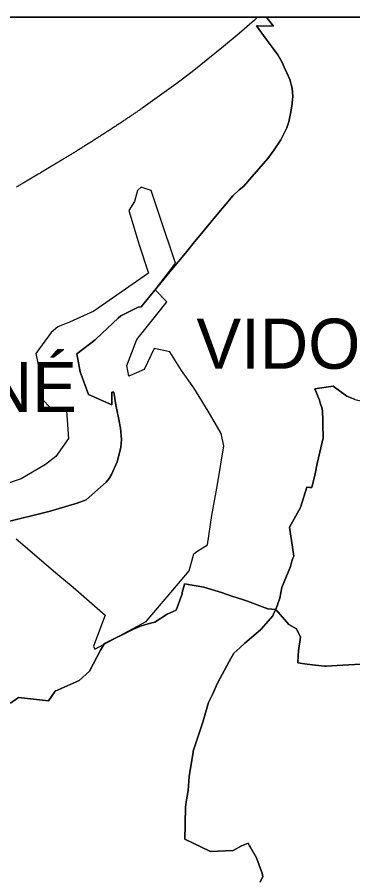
# Model space of a CAD drawing. Extents: x -759276 to -751881, y -1176141 to -1171097.
# Drawn here: x -755760 to -754995, y -1173060 to -1171097 of the extents above; entities that cross this region are included whole.
import ezdxf

# ---------------------------------------------------------------- set-up
doc = ezdxf.new("R2010")
doc.units = 0
for name, color, linetype in [('A_HRU', 7, 'Continuous'), ('A_OBCE', 7, 'Continuous'), ('A_SILNICE', 7, 'Continuous'), ('A_USES', 7, 'Continuous'), ('AA_vyrezy', 7, 'Continuous')]:
    doc.layers.add(name, color=color, linetype=linetype)

msp = doc.modelspace()

# ---------------------------------------------------------------- linework, layer by layer
at = {"layer": 'A_HRU'}
for points in [[(-759275.6, -1176140.6), (-759275.6, -1171097.2), (-751880.9, -1171097.2), (-751880.9, -1176140.6)], [(-751880.9, -1172828.3), (-753894.3, -1172828.3), (-753894.3, -1171097.2), (-759275.6, -1171097.2), (-759275.6, -1176140.6), (-753894.3, -1176140.6), (-753894.3, -1174884.8), (-751880.9, -1174884.8)]]:
    msp.add_lwpolyline(points, close=True, dxfattribs=at)
at = {"layer": 'A_OBCE'}
for p, q in [((-755191.2, -1171097.2), (-756678.2, -1171097.2)), ((-755191.2, -1171097.2), (-755189.6, -1171099.3)), ((-754699.6, -1171097.2), (-755191.2, -1171097.2)), ((-755189.6, -1171099.3), (-755181.2, -1171110.1)), ((-755214.5, -1171117.1), (-755192, -1171147)), ((-755181.2, -1171110.1), (-755175.1, -1171118)), ((-755192, -1171147), (-755187.5, -1171153.1)), ((-755165.3, -1171183.2), (-755156.2, -1171199.1)), ((-755156.2, -1171199.1), (-755151, -1171211.1)), ((-755138.5, -1171239.2), (-755132.9, -1171259.5)), ((-755131.7, -1171278), (-755132.9, -1171259.5)), ((-755132.9, -1171259.5), (-755131.7, -1171278)), ((-755133.5, -1171300.6), (-755131.7, -1171278)), ((-755131.7, -1171278), (-755133.5, -1171300.6)), ((-755144.9, -1171349.4), (-755140.5, -1171336.4)), ((-755140.5, -1171336.4), (-755144.9, -1171349.4)), ((-755144.9, -1171349.4), (-755153.8, -1171368.4)), ((-755153.8, -1171368.4), (-755158.5, -1171377.5)), ((-755158.5, -1171377.5), (-755174, -1171400.1)), ((-755174, -1171400.1), (-755188.2, -1171419.5)), ((-755188.2, -1171419.5), (-755208.8, -1171443.2)), ((-755208.8, -1171443.2), (-755229.7, -1171466.9)), ((-755229.7, -1171466.9), (-755243.2, -1171482.6)), ((-755253.7, -1171491.7), (-755268.3, -1171505.3)), ((-755243.2, -1171482.6), (-755253.7, -1171491.7)), ((-755268.3, -1171505.3), (-755276.4, -1171515.1)), ((-755296.6, -1171538.4), (-755279.2, -1171518.2)), ((-755279.2, -1171518.2), (-755296.6, -1171538.4)), ((-755276.4, -1171515.1), (-755279.2, -1171518.2)), ((-755408.1, -1171673.9), (-755375.8, -1171635.8)), ((-755411.9, -1171678.4), (-755408.1, -1171673.9)), ((-755529.5, -1171784.5), (-755579.6, -1171831.8)), ((-755624.1, -1171865.9), (-755582.1, -1171833.7)), ((-755624.1, -1171865.9), (-755616.1, -1171906.8)), ((-755039.3, -1171939.7), (-755081.3, -1171945.8)), ((-755008.6, -1171962.4), (-755039.3, -1171939.7)), ((-755544.1, -1171982), (-755544.3, -1171953.2)), ((-755070.9, -1171971.5), (-755081.3, -1171945.8)), ((-755081.3, -1171945.8), (-755070.9, -1171971.5)), ((-755067.9, -1171980.7), (-755070.9, -1171971.5)), ((-755065.4, -1171988.3), (-755067.9, -1171980.7)), ((-755527.8, -1172015.9), (-755533.2, -1171989.5)), ((-755533.2, -1171989.5), (-755527.8, -1172015.9)), ((-755062.8, -1172018.3), (-755063.3, -1172028)), ((-755523.6, -1172079.7), (-755532.1, -1172112.1)), ((-755069.9, -1172090.5), (-755075.9, -1172116.5)), ((-755532.1, -1172112.1), (-755544.6, -1172140.9)), ((-755075.9, -1172116.5), (-755080.1, -1172140.1)), ((-755080.1, -1172140.1), (-755088.2, -1172170.7)), ((-755556.8, -1172158.7), (-755602.9, -1172199.5)), ((-755556.8, -1172158.7), (-755550, -1172150.3)), ((-755099.4, -1172170.3), (-755113.8, -1172216.8)), ((-755098.4, -1172170.4), (-755092.7, -1172170.6)), ((-755088.2, -1172170.7), (-755092.7, -1172170.6)), ((-755602.9, -1172199.5), (-755622.9, -1172206.8)), ((-755685.1, -1172225.2), (-755622.9, -1172206.8)), ((-755622.9, -1172206.8), (-755685.1, -1172225.2)), ((-755139.1, -1172261.5), (-755113.8, -1172216.8)), ((-755113.8, -1172216.8), (-755139.1, -1172261.5)), ((-755788.6, -1172250.8), (-755685.1, -1172225.2)), ((-755685.1, -1172225.2), (-755788.6, -1172250.8)), ((-755139.1, -1172261.5), (-755129.2, -1172327.7)), ((-755129.2, -1172327.7), (-755131, -1172332.4)), ((-755379.4, -1172394.5), (-755383.6, -1172410.6)), ((-755383.6, -1172410.6), (-755379.4, -1172394.5)), ((-755379.4, -1172394.5), (-755378.4, -1172390.8)), ((-755245.8, -1172427), (-755270.4, -1172418.9)), ((-755270.4, -1172418.9), (-755245.8, -1172427)), ((-755160.9, -1172423.4), (-755169.9, -1172449.7)), ((-755418.2, -1172460), (-755397.6, -1172451)), ((-755174.6, -1172458.1), (-755169.9, -1172449.7)), ((-755169.9, -1172449.7), (-755140.7, -1172483.7)), ((-755418.2, -1172460), (-755446.1, -1172478.2)), ((-755446.1, -1172478.2), (-755418.2, -1172460)), ((-755177.3, -1172463.6), (-755203.3, -1172494.5)), ((-755495, -1172494.6), (-755560.6, -1172527.4)), ((-755560.6, -1172527.4), (-755495, -1172494.6)), ((-755495, -1172494.6), (-755479.1, -1172487.6)), ((-755479.1, -1172487.6), (-755469, -1172484.6)), ((-755469, -1172484.6), (-755455.8, -1172480.6)), ((-755455.8, -1172480.6), (-755446.1, -1172478.2)), ((-755203.3, -1172494.5), (-755205.1, -1172496)), ((-755241, -1172526.4), (-755205.1, -1172496)), ((-755205.1, -1172496), (-755241, -1172526.4)), ((-755560.6, -1172527.4), (-755570, -1172542.4)), ((-755570, -1172542.4), (-755560.6, -1172527.4)), ((-755241.6, -1172527), (-755241, -1172526.4)), ((-755241, -1172526.4), (-755241.6, -1172527)), ((-755570, -1172542.4), (-755595.4, -1172590.4)), ((-755595.4, -1172590.4), (-755570, -1172542.4)), ((-755276.3, -1172568.6), (-755302.9, -1172617.6)), ((-755119.3, -1172554.4), (-755120.2, -1172571.1)), ((-755120.2, -1172571.1), (-755104.4, -1172573.2)), ((-755618.7, -1172611.4), (-755595.4, -1172590.4)), ((-755104.4, -1172573.2), (-755086.9, -1172575.5)), ((-755055.1, -1172579), (-755017.6, -1172576.6)), ((-754976.1, -1172574.1), (-755017.6, -1172576.6)), ((-755017.6, -1172576.6), (-754976.1, -1172574.1)), ((-755673.7, -1172636), (-755618.7, -1172611.4)), ((-755302.9, -1172617.6), (-755314.9, -1172643.6)), ((-755775.2, -1172663.6), (-755756.9, -1172650.2)), ((-755314.9, -1172643.6), (-755323.3, -1172661.6)), ((-755367.7, -1172830.6), (-755358.9, -1172774.9)), ((-755358.9, -1172774.9), (-755367.7, -1172830.6)), ((-755358.7, -1172773.3), (-755358.9, -1172774.9)), ((-755369.8, -1172862.6), (-755367.7, -1172830.6)), ((-755367.7, -1172830.6), (-755369.8, -1172862.6)), ((-755369.8, -1172862.6), (-755374.3, -1172888.7)), ((-755376.8, -1172937.9), (-755376.4, -1172901.1)), ((-755376.4, -1172901.1), (-755376.8, -1172937.9)), ((-755374.3, -1172888.7), (-755376.4, -1172901.1)), ((-755377.5, -1172973.7), (-755376.9, -1172941.1)), ((-755376.9, -1172941.1), (-755377.5, -1172973.7)), ((-755376.9, -1172941.1), (-755376.8, -1172937.9)), ((-755376.8, -1172937.9), (-755376.9, -1172941.1)), ((-755377.5, -1172973.7), (-755319.1, -1173002.3)), ((-755319.1, -1173002.3), (-755267.7, -1172999.5)), ((-755267.7, -1172999.5), (-755248.1, -1172989.1)), ((-755229.9, -1172989), (-755228.3, -1172991.7)), ((-755228.3, -1172991.7), (-755214.3, -1173016.4)), ((-755206, -1173071.7), (-755199.5, -1173059.1)), ((-755199.5, -1173059.1), (-755206, -1173071.7))]:
    msp.add_line(p, q, dxfattribs=at)
for points in [[(-755187.5, -1171153.1), (-755192, -1171147), (-755214.5, -1171117.1), (-755212.9, -1171117.2), (-755175.1, -1171118), (-755181.2, -1171110.1), (-755189.6, -1171099.3), (-755191.2, -1171097.2)], [(-755175.1, -1171118), (-755212.9, -1171117.2), (-755214.5, -1171117.1)], [(-755151, -1171211.1), (-755156.2, -1171199.1), (-755165.3, -1171183.2), (-755176.1, -1171168.3), (-755187.5, -1171153.1)], [(-755187.5, -1171153.1), (-755176.1, -1171168.3), (-755165.3, -1171183.2)], [(-755132.9, -1171259.5), (-755138.5, -1171239.2), (-755144.7, -1171224.3), (-755151, -1171211.1)], [(-755151, -1171211.1), (-755144.7, -1171224.3), (-755138.5, -1171239.2)], [(-755140.5, -1171336.4), (-755136.4, -1171317.4), (-755133.5, -1171300.6)], [(-755133.5, -1171300.6), (-755136.4, -1171317.4), (-755140.5, -1171336.4)], [(-755253.7, -1171491.7), (-755243.2, -1171482.6), (-755229.7, -1171466.9), (-755208.8, -1171443.2), (-755188.2, -1171419.5), (-755174, -1171400.1), (-755158.5, -1171377.5), (-755153.8, -1171368.4), (-755144.9, -1171349.4)], [(-755279.2, -1171518.2), (-755276.4, -1171515.1), (-755268.3, -1171505.3), (-755253.7, -1171491.7)], [(-755296.6, -1171538.4), (-755358.7, -1171613.7), (-755375.8, -1171635.8), (-755408.1, -1171673.9), (-755411.9, -1171678.4), (-755477.4, -1171758.1), (-755483.7, -1171758.9), (-755523.5, -1171778.9), (-755529.5, -1171784.5)], [(-755375.8, -1171635.8), (-755358.7, -1171613.7), (-755296.6, -1171538.4)], [(-755529.5, -1171784.5), (-755523.5, -1171778.9), (-755483.7, -1171758.9), (-755477.4, -1171758.1), (-755411.9, -1171678.4)], [(-755582.1, -1171833.7), (-755579.6, -1171831.8), (-755529.5, -1171784.5)], [(-755579.6, -1171831.8), (-755582.1, -1171833.7), (-755624.1, -1171865.9)], [(-755597.5, -1171958.4), (-755616.1, -1171906.8), (-755624.1, -1171865.9)], [(-755616.1, -1171906.8), (-755597.5, -1171958.4), (-755544.1, -1171982)], [(-755081.3, -1171945.8), (-755039.3, -1171939.7), (-755008.6, -1171962.4)], [(-755533.2, -1171989.5), (-755534.8, -1171981.9), (-755539.3, -1171953.3), (-755544.3, -1171953.2), (-755544.1, -1171982), (-755597.5, -1171958.4)], [(-755544.3, -1171953.2), (-755539.3, -1171953.3), (-755534.8, -1171981.9), (-755533.2, -1171989.5)], [(-755008.6, -1171962.4), (-754992.9, -1171968.8), (-754990.3, -1171969.9), (-754951.7, -1171978.1)], [(-754990.3, -1171969.9), (-754992.9, -1171968.8), (-755008.6, -1171962.4)], [(-755070.9, -1171971.5), (-755067.9, -1171980.7), (-755065.4, -1171988.3)], [(-755075.9, -1172116.5), (-755069.9, -1172090.5), (-755062.3, -1172057.3), (-755063.3, -1172028), (-755062.8, -1172018.3), (-755064, -1171996.1), (-755065.4, -1171988.3)], [(-755065.4, -1171988.3), (-755064, -1171996.1), (-755062.8, -1172018.3)], [(-755522.4, -1172061.4), (-755524.7, -1172035.5), (-755527.8, -1172015.9)], [(-755527.8, -1172015.9), (-755524.7, -1172035.5), (-755522.4, -1172061.4), (-755523.6, -1172079.7)], [(-755063.3, -1172028), (-755062.3, -1172057.3), (-755069.9, -1172090.5)], [(-755532.1, -1172112.1), (-755523.6, -1172079.7), (-755522.4, -1172061.4)], [(-755550, -1172150.3), (-755544.6, -1172140.9), (-755532.1, -1172112.1)], [(-755092.7, -1172170.6), (-755088.2, -1172170.7), (-755080.1, -1172140.1), (-755075.9, -1172116.5)], [(-755544.6, -1172140.9), (-755550, -1172150.3), (-755556.8, -1172158.7)], [(-755622.9, -1172206.8), (-755602.9, -1172199.5), (-755556.8, -1172158.7)], [(-755113.8, -1172216.8), (-755099.4, -1172170.3), (-755098.4, -1172170.4)], [(-755092.7, -1172170.6), (-755098.4, -1172170.4), (-755099.4, -1172170.3)], [(-755137, -1172351.6), (-755133.5, -1172338.9), (-755131, -1172332.4), (-755129.2, -1172327.7), (-755139.1, -1172261.5)], [(-755131, -1172332.4), (-755133.5, -1172338.9), (-755137, -1172351.6)], [(-755169.9, -1172449.7), (-755160.9, -1172423.4), (-755156.5, -1172399.1), (-755137, -1172351.6)], [(-755137, -1172351.6), (-755156.5, -1172399.1), (-755160.9, -1172423.4)], [(-755270.4, -1172418.9), (-755294.4, -1172411), (-755334, -1172398.2), (-755378.4, -1172390.8), (-755379.4, -1172394.5)], [(-755378.4, -1172390.8), (-755334, -1172398.2), (-755294.4, -1172411), (-755270.4, -1172418.9)], [(-755383.6, -1172410.6), (-755383.7, -1172414), (-755397.6, -1172451), (-755418.2, -1172460)], [(-755397.6, -1172451), (-755383.7, -1172414), (-755383.6, -1172410.6)], [(-755234.7, -1172430.7), (-755236.9, -1172429.9), (-755245.8, -1172427)], [(-755245.8, -1172427), (-755236.9, -1172429.9), (-755234.7, -1172430.7)], [(-755169.9, -1172449.7), (-755188.6, -1172448.2), (-755200.6, -1172443.7), (-755234.7, -1172430.7)], [(-755234.7, -1172430.7), (-755200.6, -1172443.7), (-755188.6, -1172448.2), (-755169.9, -1172449.7)], [(-755169.9, -1172449.7), (-755174.6, -1172458.1), (-755177.3, -1172463.6)], [(-755118.7, -1172543.7), (-755113.6, -1172513), (-755122.9, -1172494), (-755140.7, -1172483.7), (-755169.9, -1172449.7)], [(-755205.1, -1172496), (-755203.3, -1172494.5), (-755177.3, -1172463.6), (-755174.6, -1172458.1)], [(-755469, -1172484.6), (-755479.1, -1172487.6), (-755495, -1172494.6)], [(-755446.1, -1172478.2), (-755455.8, -1172480.6), (-755469, -1172484.6)], [(-755140.7, -1172483.7), (-755122.9, -1172494), (-755113.6, -1172513)], [(-755113.6, -1172513), (-755118.7, -1172543.7), (-755119.3, -1172554.4)], [(-755241.6, -1172527), (-755252.3, -1172536.7), (-755265.6, -1172548.9), (-755276.3, -1172568.6)], [(-755265.6, -1172548.9), (-755252.3, -1172536.7), (-755241.6, -1172527)], [(-755302.9, -1172617.6), (-755276.3, -1172568.6), (-755265.6, -1172548.9)], [(-755120.2, -1172571.1), (-755119.3, -1172554.4), (-755118.7, -1172543.7)], [(-755017.6, -1172576.6), (-755055.1, -1172579), (-755059.2, -1172579), (-755086.9, -1172575.5), (-755104.4, -1172573.2), (-755120.2, -1172571.1)], [(-755595.4, -1172590.4), (-755618.7, -1172611.4), (-755673.7, -1172636), (-755688.4, -1172658)], [(-755086.9, -1172575.5), (-755059.2, -1172579), (-755055.1, -1172579)], [(-755323.3, -1172661.6), (-755314.9, -1172643.6), (-755302.9, -1172617.6)], [(-755688.4, -1172658), (-755756.9, -1172650.2), (-755775.2, -1172663.6)], [(-755756.9, -1172650.2), (-755688.4, -1172658), (-755673.7, -1172636)], [(-755358.9, -1172774.9), (-755358.7, -1172773.3), (-755336.7, -1172707), (-755323.3, -1172661.6)], [(-755323.3, -1172661.6), (-755336.7, -1172707), (-755358.7, -1172773.3)], [(-755376.4, -1172901.1), (-755374.3, -1172888.7), (-755369.8, -1172862.6)], [(-755248.1, -1172989.1), (-755267.7, -1172999.5), (-755319.1, -1173002.3), (-755377.5, -1172973.7)], [(-755229.9, -1172989), (-755233.2, -1172983.1), (-755248.1, -1172989.1)], [(-755248.1, -1172989.1), (-755233.2, -1172983.1), (-755229.9, -1172989)], [(-755214.3, -1173016.4), (-755228.3, -1172991.7), (-755229.9, -1172989)], [(-755199.5, -1173059.1), (-755201.1, -1173051.5), (-755204.8, -1173041.6), (-755214.3, -1173016.4)], [(-755214.3, -1173016.4), (-755204.8, -1173041.6), (-755201.1, -1173051.5), (-755199.5, -1173059.1)]]:
    msp.add_lwpolyline(points, dxfattribs=at)
at = {"layer": 'A_SILNICE'}
msp.add_lwpolyline([(-755211.9, -1171097.2), (-755219.1, -1171103.7), (-755253.8, -1171134.1), (-755289.1, -1171163.9), (-755324.9, -1171193.1), (-755361.2, -1171221.7), (-755398, -1171249.7), (-755435.2, -1171277), (-755473, -1171303.7), (-755474.8, -1171305), (-755476.6, -1171306.2), (-755478.4, -1171307.5), (-755480.2, -1171308.7), (-755482, -1171310), (-755483.8, -1171311.2), (-755485.6, -1171312.5), (-755487.4, -1171313.7), (-755489.3, -1171315), (-755491.1, -1171316.2), (-755492.9, -1171317.4), (-755494.7, -1171318.7), (-755496.5, -1171319.9), (-755498.3, -1171321.2), (-755500.2, -1171322.4), (-755502, -1171323.6), (-755503.8, -1171324.9), (-755505.6, -1171326.1), (-755507.5, -1171327.3), (-755509.3, -1171328.5), (-755511.1, -1171329.8), (-755512.9, -1171331), (-755514.8, -1171332.2), (-755516.6, -1171333.4), (-755518.4, -1171334.7), (-755520.3, -1171335.9), (-755522.1, -1171337.1), (-755523.9, -1171338.3), (-755525.7, -1171339.5), (-755527.6, -1171340.8), (-755529.4, -1171342), (-755531.3, -1171343.2), (-755533.1, -1171344.4), (-755534.9, -1171345.6), (-755536.8, -1171346.8), (-755538.6, -1171348), (-755540.4, -1171349.2), (-755542.3, -1171350.4), (-755544.1, -1171351.6), (-755546, -1171352.8), (-755547.8, -1171354), (-755549.7, -1171355.2), (-755551.5, -1171356.4), (-755553.3, -1171357.6), (-755555.2, -1171358.8), (-755557, -1171360), (-755558.9, -1171361.2), (-755560.7, -1171362.4), (-755562.6, -1171363.6), (-755564.4, -1171364.8), (-755566.3, -1171366), (-755568.1, -1171367.2), (-755570, -1171368.4), (-755571.8, -1171369.6), (-755573.7, -1171370.7), (-755575.5, -1171371.9), (-755577.4, -1171373.1), (-755579.3, -1171374.3), (-755581.1, -1171375.5), (-755583, -1171376.7), (-755584.8, -1171377.8), (-755586.7, -1171379), (-755588.5, -1171380.2), (-755590.4, -1171381.4), (-755592.3, -1171382.5), (-755594.1, -1171383.7), (-755596, -1171384.9), (-755597.8, -1171386.1), (-755599.7, -1171387.2), (-755601.6, -1171388.4), (-755603.4, -1171389.6), (-755605.3, -1171390.7), (-755607.2, -1171391.9), (-755609, -1171393.1), (-755610.9, -1171394.2), (-755612.8, -1171395.4), (-755614.6, -1171396.6), (-755616.5, -1171397.7), (-755618.4, -1171398.9), (-755620.2, -1171400), (-755622.1, -1171401.2), (-755624, -1171402.4), (-755625.8, -1171403.5), (-755627.7, -1171404.7), (-755629.6, -1171405.8), (-755631.5, -1171407), (-755633.3, -1171408.1), (-755635.2, -1171409.3), (-755637.1, -1171410.5), (-755639, -1171411.6), (-755640.8, -1171412.8), (-755642.7, -1171413.9), (-755644.6, -1171415.1), (-755646.5, -1171416.2), (-755648.3, -1171417.3), (-755650.2, -1171418.5), (-755652.1, -1171419.6), (-755654, -1171420.8), (-755655.8, -1171421.9), (-755657.7, -1171423.1), (-755659.6, -1171424.2), (-755661.5, -1171425.4), (-755663.4, -1171426.5), (-755665.2, -1171427.6), (-755667.1, -1171428.8), (-755669, -1171429.9), (-755670.9, -1171431.1), (-755672.8, -1171432.2), (-755674.7, -1171433.3), (-755676.5, -1171434.5), (-755678.4, -1171435.6), (-755680.3, -1171436.7), (-755682.2, -1171437.9), (-755684.1, -1171439), (-755686, -1171440.1), (-755687.9, -1171441.3), (-755689.7, -1171442.4), (-755691.6, -1171443.5), (-755693.5, -1171444.7), (-755695.4, -1171445.8), (-755697.3, -1171446.9), (-755699.2, -1171448), (-755701.1, -1171449.2), (-755703, -1171450.3), (-755704.9, -1171451.4), (-755706.7, -1171452.6), (-755708.6, -1171453.7), (-755710.5, -1171454.8), (-755712.4, -1171455.9), (-755714.3, -1171457.1), (-755716.2, -1171458.2), (-755718.1, -1171459.3), (-755720, -1171460.4), (-755721.9, -1171461.5), (-755723.8, -1171462.7), (-755725.7, -1171463.8), (-755727.6, -1171464.9), (-755729.4, -1171466), (-755731.3, -1171467.1), (-755733.2, -1171468.3), (-755735.1, -1171469.4), (-755737, -1171470.5), (-755738.9, -1171471.6), (-755740.8, -1171472.7), (-755742.7, -1171473.9), (-755744.6, -1171475), (-755746.5, -1171476.1), (-755748.4, -1171477.2), (-755750.3, -1171478.3), (-755752.2, -1171479.4), (-755754.1, -1171480.5), (-755756, -1171481.7), (-755757.9, -1171482.8), (-755759.8, -1171483.9), (-755761.7, -1171485)], dxfattribs=at)
at = {"layer": 'A_USES'}
msp.add_lwpolyline([(-755762.3, -1172288), (-755667, -1172369.5), (-755632, -1172398.5), (-755559.6, -1172462.5), (-755585.6, -1172532.9), (-755583.2, -1172540.2), (-755465.9, -1172477), (-755392.4, -1172390.2), (-755368.1, -1172361.2), (-755357.1, -1172322.4), (-755350.3, -1172317.4), (-755326.2, -1172302.2), (-755316, -1172235.1), (-755303.5, -1172164.1), (-755288.7, -1172075.9), (-755295, -1172047.8), (-755324.6, -1171997), (-755357.4, -1171943.2), (-755385.5, -1171904.1), (-755412, -1171861.2), (-755447.2, -1171853.4), (-755470.6, -1171901.8), (-755505.7, -1171916.6), (-755509.6, -1171892.1), (-755487.3, -1171832.9), (-755432, -1171764.4), (-755418.8, -1171747.3), (-755445.1, -1171719.6), (-755417.3, -1171683), (-755399.1, -1171659.1), (-755435.4, -1171549.6), (-755454.4, -1171492.5), (-755477.3, -1171484.9), (-755485.7, -1171492.5), (-755492.5, -1171517.6), (-755505.5, -1171538.2), (-755481.9, -1171616.7), (-755460.5, -1171681.5), (-755585.3, -1171768.7), (-755640.9, -1171793.7), (-755667.3, -1171804.2), (-755682.8, -1171817.3), (-755717.6, -1171864.7), (-755703.8, -1171931.4), (-755701.2, -1171970.5), (-755685.6, -1171987.3), (-755647.4, -1171995.7), (-755642.6, -1172059.4), (-755671.6, -1172100.5), (-755695.2, -1172118.1), (-755750.8, -1172150.8), (-755824, -1172175.2)], dxfattribs=at)

# ---------------------------------------------------------------- texts
at = {"layer": 'AA_vyrezy'}
msp.add_text('VIDOV', height=114.37, dxfattribs=at).set_placement((-755351.3, -1171899.8))
msp.add_text('ROUDNÉ', height=114.37, rotation=360, dxfattribs=at).set_placement((-756286.5, -1171998.9))

doc.saveas('drawing.dxf')
